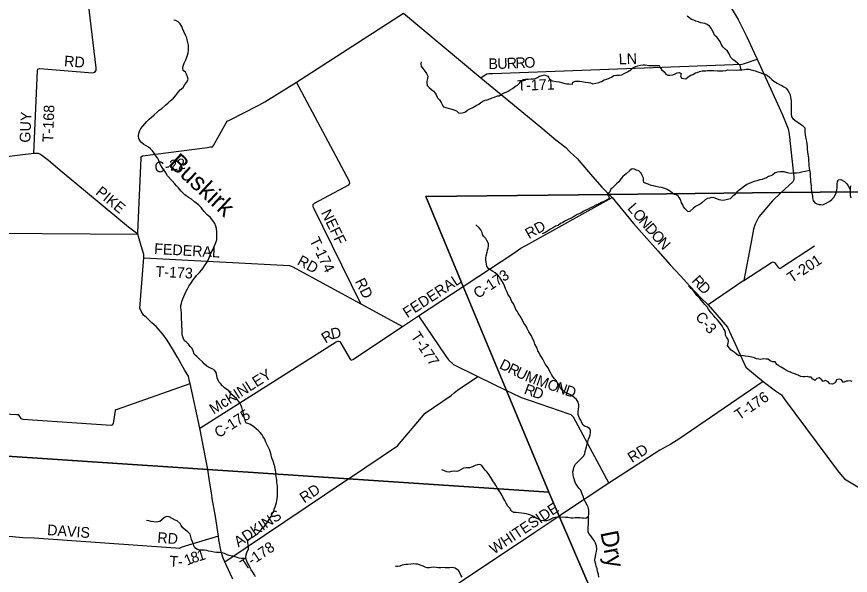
# Model space of a CAD drawing. Extents: x 1643459 to 2064572, y 425441 to 780708.
# Drawn here: x 1766596 to 1790021, y 620966 to 636662 of the extents above; entities that cross this region are included whole.
import ezdxf

# ---------------------------------------------------------------- set-up
doc = ezdxf.new("R2010")
doc.units = 0
for name, color, linetype in [('GM_X_City_Street', 7, 'Continuous'), ('GM_X_Interchange_Ramps', 7, 'Continuous'), ('GM_X_Major_River', 7, 'Continuous'), ('GM_X_Major_River_Text', 7, 'Continuous'), ('GM_X_Minor_Lake', 7, 'Continuous'), ('GM_X_Section_Text', 7, 'Continuous'), ('GM_X_US_Route', 7, 'Continuous')]:
    doc.layers.add(name, color=color, linetype=linetype)

msp = doc.modelspace()

# ---------------------------------------------------------------- linework, layer by layer
at = {"layer": 'GM_X_City_Street'}
for points in [[(1790269, 631741), (1788081, 631718), (1783242, 631666), (1778092, 631612), (1779143, 629082), (1780359, 626159), (1781545, 623306), (1775923, 623680), (1771965, 623943), (1758715, 624823), (1757178, 624925), (1757203, 625316), (1757453, 629228), (1757708, 633208), (1757977, 636642), (1758154, 639332)], [(1790575, 602316), (1789055, 605851), (1787632, 609158), (1785470, 614182), (1781837, 622626), (1781545, 623306), (1780359, 626159), (1779143, 629082), (1778092, 631612), (1783242, 631666), (1788081, 631718), (1790269, 631741)], [(1755032, 592905), (1755763, 604727), (1756758, 618359), (1756763, 618445), (1757178, 624925), (1758715, 624823), (1771965, 623943), (1775923, 623680), (1781545, 623306), (1781837, 622626), (1785470, 614182), (1787632, 609158), (1789055, 605851), (1790575, 602316), (1791118, 601055), (1793558, 602184), (1795084, 602890), (1794631, 595981)]]:
    msp.add_lwpolyline(points, dxfattribs=at)
at = {"layer": 'GM_X_Major_River_Text'}
for points in [[(1767083, 632818), (1767179, 635150), (1767195, 635186), (1767247, 635204), (1768723, 635088), (1768794, 635100), (1768826, 635150), (1768828, 635224), (1768475, 638203), (1767992, 642727)], [(1779643, 634945), (1779761, 635027), (1779809, 635055), (1779864, 635069), (1779976, 635068), (1786986, 635330), (1787052, 635344), (1787403, 635467)], [(1776267, 628598), (1774935, 631300), (1774929, 631339), (1774929, 631387), (1774969, 631421), (1775926, 631941), (1775954, 631971), (1775952, 632031), (1774462, 634825)], [(1787032, 629249), (1787808, 629758), (1787852, 629776), (1787892, 629758), (1788003, 629603), (1788043, 629589), (1788071, 629602), (1789018, 630222)], [(1770165, 629889), (1774267, 629667), (1774337, 629647), (1776267, 628598), (1777440, 627960)], [(1777890, 628257), (1778654, 627128), (1778733, 627019), (1778875, 626890), (1779559, 626553), (1780359, 626159), (1780500, 626092)], [(1775816, 623609), (1775923, 623680), (1777298, 624601), (1778078, 625524), (1778808, 626018), (1778887, 626097), (1778985, 626171), (1779559, 626553)], [(1787576, 626408), (1785201, 624793), (1784978, 624653), (1784670, 624480), (1783239, 623558), (1781934, 622690)], [(1758421, 625192), (1759118, 625175), (1759180, 625174), (1759214, 625196), (1759235, 625280), (1759284, 625860), (1759310, 625902), (1759370, 625900), (1766599, 625487), (1766639, 625483), (1766717, 625372), (1766771, 625352), (1769252, 625185), (1769288, 625191), (1769317, 625233), (1769369, 625594), (1769393, 625623), (1769429, 625637), (1771468, 626355)], [(1780500, 626092), (1780771, 625964), (1781023, 625874), (1782111, 625502), (1782165, 625485), (1782233, 625415), (1783239, 623558)], [(1772443, 621349), (1775816, 623609)], [(1772265, 622062), (1771334, 621784), (1771222, 621751), (1771159, 621721), (1771061, 621727), (1767086, 622006), (1766767, 622024), (1766477, 622043), (1766074, 622089), (1765375, 622185), (1764879, 622258), (1764486, 622292), (1763829, 622329), (1762692, 622399), (1762500, 622430), (1762426, 622474), (1762366, 622549), (1762350, 622609), (1762308, 622615), (1760568, 622684)], [(1781934, 622690), (1781837, 622626), (1781604, 622471), (1781160, 622171), (1779067, 620775), (1773925, 617348)]]:
    msp.add_lwpolyline(points, dxfattribs=at)
at = {"layer": 'GM_X_Minor_Lake'}
for points in [[(1786244, 637616), (1786618, 637001), (1786872, 636581), (1787110, 636098), (1787316, 635642), (1787403, 635467), (1788112, 633901), (1788235, 633607), (1788278, 633507), (1788306, 633358), (1788432, 632153), (1788432, 632075), (1788402, 632022), (1788081, 631718), (1787834, 631484), (1787452, 631039), (1787349, 630830), (1787339, 630801)], [(1770002, 630601), (1770093, 632687), (1770093, 632721), (1770134, 632749), (1771962, 632990), (1772032, 633004), (1772074, 633002), (1772101, 633006), (1772127, 633040), (1772487, 633676), (1772513, 633722), (1772573, 633755), (1773397, 634171), (1773574, 634266), (1774462, 634825), (1777468, 636763)], [(1777468, 636763), (1779643, 634945), (1780949, 633862), (1781378, 633511), (1781747, 633198), (1782023, 632988), (1782140, 632869), (1782345, 632675), (1782447, 632557), (1782718, 632238), (1783038, 631872), (1783242, 631666), (1783288, 631620)], [(1770000, 630549), (1769738, 630751), (1767875, 632293), (1767488, 632617), (1767305, 632763), (1767251, 632801), (1767205, 632821), (1767083, 632818), (1766239, 632718), (1766124, 632716), (1765966, 632741), (1765594, 632819), (1764734, 633082), (1764288, 633225), (1763876, 633369), (1762914, 633685), (1762390, 633870), (1761928, 634031), (1761582, 634167), (1760684, 634572), (1760184, 634781)], [(1779254, 629155), (1780534, 629999), (1780767, 630154), (1780900, 630229), (1783325, 631583)], [(1783288, 631620), (1783325, 631583), (1783925, 630854), (1784231, 630514), (1784608, 630087), (1784962, 629692), (1785249, 629378), (1785510, 629088), (1785835, 628745), (1786024, 628565)], [(1758569, 629508), (1760488, 630050), (1760613, 630088), (1760956, 630230), (1761763, 630549), (1761833, 630579), (1761938, 630603), (1770000, 630549), (1770002, 630601), (1770002, 630601)], [(1787339, 630801), (1787339, 630800), (1787302, 630689), (1787221, 630277), (1787032, 629249), (1786024, 628565)], [(1772076, 623215), (1772076, 623217), (1772011, 623620), (1771965, 623943), (1771740, 625096), (1771468, 626355), (1771455, 626416), (1771421, 626560), (1771326, 626717), (1771121, 627073), (1770977, 627329), (1770828, 627572), (1770702, 627737), (1770513, 627957), (1770393, 628064), (1770234, 628221), (1770164, 628280), (1770095, 628390), (1770059, 628469), (1770162, 629778), (1770165, 629889), (1770167, 629978), (1770096, 630222), (1770000, 630549)], [(1777440, 627960), (1777890, 628257), (1779143, 629082), (1779254, 629155)], [(1786024, 628565), (1786568, 627941), (1787089, 626817), (1787576, 626408), (1787923, 626151), (1788091, 626036), (1788162, 625929), (1789662, 623912), (1789748, 623811), (1789861, 623680), (1791597, 622627), (1791717, 622548), (1791760, 622488), (1791917, 622258), (1792684, 620737), (1793347, 619452), (1794514, 618662)], [(1771740, 625096), (1775578, 627522), (1775616, 627544), (1775642, 627548), (1775680, 627538), (1775970, 627043), (1775996, 627012), (1776044, 627034), (1777440, 627960)], [(1772673, 620857), (1772481, 621261), (1772443, 621349), (1772402, 621446), (1772347, 621623), (1772281, 621964), (1772265, 622062), (1772180, 622617), (1772090, 623129), (1772076, 623215)]]:
    msp.add_lwpolyline(points, dxfattribs=at)
at = {"layer": 'GM_X_US_Route'}
for points in [[(1772105, 630112), (1772145, 630202), (1772180, 630285), (1772217, 630393), (1772225, 630461), (1772218, 630519), (1772221, 630620), (1772215, 630710), (1772194, 630778), (1772160, 630847), (1772103, 630941), (1772031, 631028), (1771949, 631095), (1771864, 631192), (1771822, 631244), (1771778, 631299), (1771715, 631367), (1771663, 631410), (1771589, 631458), (1771507, 631531), (1771421, 631584), (1771324, 631658), (1771216, 631763), (1771139, 631854), (1771087, 631911), (1771043, 631967), (1770970, 632054), (1770838, 632187), (1770789, 632270), (1770757, 632320), (1770725, 632370), (1770687, 632425), (1770634, 632501), (1770608, 632564), (1770581, 632644), (1770557, 632699), (1770501, 632763), (1770462, 632830), (1770412, 632892), (1770360, 632945), (1770298, 632993), (1770237, 633030), (1770173, 633066), (1770101, 633125), (1770051, 633189), (1770025, 633239), (1770024, 633312), (1770033, 633384), (1770059, 633468), (1770088, 633522), (1770142, 633586), (1770193, 633650), (1770253, 633714), (1770316, 633778), (1770389, 633838), (1770457, 633908), (1770540, 633981), (1770603, 634031), (1770675, 634085), (1770774, 634177), (1770849, 634243), (1770913, 634297), (1771000, 634374), (1771057, 634438), (1771146, 634548), (1771192, 634602), (1771273, 634674), (1771321, 634752), (1771380, 634820), (1771411, 634910), (1771397, 634972), (1771366, 635049), (1771336, 635101), (1771276, 635154), (1771267, 635222), (1771273, 635272), (1771300, 635352), (1771346, 635449), (1771381, 635521), (1771397, 635581), (1771414, 635649), (1771427, 635717), (1771429, 635787), (1771420, 635862), (1771406, 635938), (1771387, 636014), (1771373, 636071), (1771337, 636141), (1771292, 636244), (1771260, 636326), (1771237, 636383), (1771187, 636457), (1771131, 636514), (1771070, 636556), (1771011, 636561)], [(1786953, 635171), (1786923, 635287), (1786863, 635349), (1786785, 635408), (1786716, 635460), (1786664, 635513), (1786632, 635569), (1786611, 635638), (1786569, 635694), (1786503, 635747), (1786437, 635811), (1786396, 635888), (1786360, 635960), (1786329, 636012), (1786275, 636079), (1786205, 636138), (1786172, 636222), (1786140, 636287), (1786112, 636337), (1786063, 636391), (1785999, 636444), (1785933, 636470), (1785881, 636483), (1785817, 636493), (1785755, 636521), (1785679, 636538), (1785627, 636560), (1785561, 636585), (1785437, 636672)], [(1777961, 635396), (1777957, 635331), (1777966, 635273), (1778010, 635203), (1778076, 635126), (1778109, 635070), (1778145, 634993), (1778142, 634925), (1778126, 634853), (1778121, 634798), (1778129, 634732), (1778191, 634668), (1778254, 634613), (1778306, 634571), (1778356, 634514), (1778384, 634464), (1778423, 634383), (1778479, 634323), (1778527, 634252), (1778550, 634190), (1778594, 634133), (1778658, 634111), (1778746, 634084), (1778798, 634070), (1778854, 634054), (1778904, 634039), (1778958, 634019), (1779014, 633962), (1779078, 633950), (1779186, 633976), (1779263, 634031), (1779331, 634075), (1779410, 634109), (1779506, 634164), (1779581, 634206), (1779637, 634250), (1779694, 634288), (1779762, 634314), (1779816, 634321), (1779891, 634349), (1779959, 634383), (1780023, 634397), (1780106, 634436), (1780156, 634442), (1780206, 634474), (1780295, 634522), (1780355, 634537), (1780410, 634573), (1780466, 634603), (1780528, 634645), (1780615, 634706), (1780673, 634736), (1780726, 634792), (1780774, 634852), (1780831, 634896), (1780895, 634906), (1780965, 634909), (1781052, 634913), (1781118, 634915), (1781172, 634926), (1781232, 634956), (1781287, 634986), (1781365, 635012), (1781427, 635031), (1781521, 634993), (1781549, 634942), (1781591, 634876), (1781653, 634859), (1781753, 634843), (1781839, 634832), (1781903, 634814), (1781997, 634787), (1782057, 634773), (1782115, 634777), (1782211, 634768), (1782228, 634818), (1782302, 634854), (1782364, 634852), (1782421, 634851), (1782473, 634841), (1782523, 634833), (1782583, 634824), (1782665, 634808), (1782717, 634803), (1782785, 634779), (1782873, 634791), (1782956, 634810), (1783032, 634840), (1783107, 634888), (1783175, 634907), (1783243, 634931), (1783310, 634963), (1783380, 635013), (1783458, 635014), (1783527, 635014), (1783603, 635030), (1783665, 635061), (1783762, 635115), (1783852, 635173), (1783913, 635223), (1783983, 635266)], [(1783983, 635266), (1784054, 635282), (1784124, 635304), (1784202, 635311), (1784258, 635307), (1784359, 635292), (1784539, 635291), (1784647, 635289), (1784675, 635236), (1784713, 635180), (1784790, 635111), (1784840, 635049), (1784892, 635019), (1784950, 635018), (1785036, 635026), (1785097, 635058), (1785153, 635081), (1785213, 635089), (1785265, 635061), (1785253, 635000), (1785278, 634932), (1785399, 634915), (1785469, 634971), (1785538, 635021), (1785592, 635037), (1785666, 635081), (1785717, 635092), (1785785, 635120), (1785857, 635140), (1785909, 635143), (1785960, 635143), (1786012, 635145), (1786078, 635149), (1786136, 635154), (1786190, 635152), (1786290, 635143), (1786346, 635141), (1786443, 635143), (1786527, 635154), (1786581, 635164), (1786814, 635163), (1786898, 635164), (1786970, 635172), (1787045, 635182), (1787099, 635185), (1787173, 635185), (1787271, 635160), (1787345, 635140), (1787419, 635109), (1787483, 635089), (1787557, 635064), (1787619, 635048), (1787687, 635023), (1787759, 634957), (1787816, 634896), (1787874, 634848), (1787970, 634793), (1788030, 634759), (1788092, 634732), (1788150, 634694), (1788214, 634651), (1788261, 634585), (1788305, 634524), (1788329, 634470), (1788338, 634390), (1788356, 634297), (1788357, 634237), (1788355, 633986), (1788357, 633934), (1788368, 633847), (1788408, 633797), (1788460, 633751), (1788610, 633651), (1788675, 633609), (1788739, 633536), (1788739, 633482), (1788740, 633418), (1788756, 633343), (1788763, 633275), (1788781, 633201), (1788791, 633150), (1788796, 633098), (1788808, 633000), (1788813, 632940), (1788819, 632867), (1788826, 632803), (1788840, 632747), (1788843, 632692), (1788849, 632616), (1788854, 632536), (1788858, 632486), (1788867, 632395), (1788881, 632319), (1788888, 632241), (1788894, 632180), (1788901, 632080), (1788905, 632024), (1788911, 631971), (1788918, 631911), (1788925, 631823), (1788931, 631769)], [(1788877, 632340), (1788833, 632329), (1788751, 632310), (1788652, 632292), (1788584, 632276), (1788512, 632269), (1788437, 632265), (1788371, 632257), (1788289, 632262), (1788221, 632284), (1788161, 632307), (1788111, 632307), (1788053, 632303), (1787978, 632292), (1787908, 632276), (1787840, 632220), (1787783, 632194), (1787725, 632167), (1787665, 632135), (1787614, 632113), (1787546, 632091), (1787476, 632080), (1787393, 632054), (1787323, 632034), (1787247, 632005), (1787182, 631979), (1787114, 631945), (1787049, 631899), (1786967, 631839), (1786898, 631790), (1786836, 631732), (1786771, 631660), (1786704, 631604), (1786642, 631546), (1786569, 631522), (1786499, 631505), (1786437, 631499), (1786385, 631505), (1786335, 631518), (1786273, 631540), (1786191, 631575), (1786119, 631579), (1786061, 631565), (1786010, 631554), (1785938, 631514), (1785851, 631430), (1785801, 631396), (1785730, 631358), (1785666, 631333), (1785605, 631275), (1785519, 631197), (1785460, 631175), (1785377, 631260), (1785337, 631320), (1785319, 631373), (1785278, 631431), (1785252, 631521), (1785197, 631606), (1785141, 631653), (1785075, 631669), (1785021, 631703), (1784967, 631754), (1784871, 631807), (1784809, 631831), (1784755, 631849), (1784705, 631862), (1784637, 631870), (1784557, 631889), (1784487, 631907), (1784429, 631923), (1784345, 631956), (1784285, 631978), (1784221, 632003), (1784209, 632055), (1784208, 632123), (1784170, 632204), (1784141, 632266), (1784083, 632333), (1784009, 632349), (1783953, 632374), (1783893, 632390), (1783824, 632336), (1783725, 632244), (1783631, 632175), (1783572, 632107), (1783513, 632025), (1783455, 631969), (1783390, 631907), (1783338, 631857), (1783287, 631813), (1783251, 631725), (1783192, 631675), (1783230, 631625), (1783255, 631556), (1783201, 631529), (1783137, 631491), (1783074, 631459), (1783024, 631437), (1782958, 631401), (1782855, 631356), (1782785, 631320)], [(1788931, 631769), (1788939, 631700), (1788954, 631620), (1788960, 631570), (1788973, 631499), (1789021, 631427), (1789077, 631408), (1789143, 631388), (1789195, 631384), (1789251, 631373), (1789324, 631417), (1789376, 631437), (1789442, 631475), (1789503, 631529), (1789572, 631609), (1789622, 631709), (1789645, 631797), (1789656, 631849), (1789650, 631915), (1789650, 631965), (1789657, 632020), (1789683, 632074), (1789753, 632091), (1789853, 632031), (1789925, 631968), (1789961, 631906), (1790015, 631810)], [(1790025, 631911), (1790016, 631833), (1790012, 631745), (1790015, 631692), (1790021, 631638), (1790032, 631570)], [(1782785, 631320), (1782724, 631290), (1782652, 631253), (1782585, 631221), (1782517, 631185), (1782448, 631141), (1782350, 631100), (1782292, 631066), (1782241, 631040), (1782189, 631004), (1782116, 630974), (1782018, 630923), (1781945, 630879), (1781879, 630847), (1781808, 630799), (1781738, 630776), (1781676, 630736), (1781599, 630688), (1781537, 630652), (1781484, 630618), (1781434, 630593), (1781362, 630565)], [(1782612, 624574), (1782629, 624660), (1782644, 624716), (1782668, 624788), (1782693, 624858), (1782707, 624910), (1782724, 624969), (1782724, 625035), (1782698, 625085), (1782632, 625126), (1782572, 625144), (1782517, 625189), (1782479, 625255), (1782445, 625325), (1782412, 625378), (1782392, 625430), (1782378, 625482), (1782377, 625561), (1782381, 625643), (1782392, 625697), (1782390, 625755), (1782363, 625850), (1782327, 625902), (1782269, 625955), (1782198, 626015), (1782120, 626056), (1782052, 626088), (1781986, 626125), (1781932, 626169), (1781878, 626238), (1781855, 626294), (1781791, 626371), (1781763, 626429), (1781702, 626498), (1781638, 626591), (1781607, 626649), (1781569, 626713), (1781529, 626796), (1781460, 626887), (1781432, 626947), (1781393, 627018), (1781355, 627084), (1781305, 627154), (1781274, 627213), (1781240, 627273), (1781217, 627350), (1781159, 627460), (1781138, 627537), (1781090, 627623), (1781067, 627692), (1781021, 627752), (1780985, 627811), (1780942, 627899), (1780910, 627970), (1780845, 628054), (1780817, 628115), (1780783, 628185), (1780746, 628250), (1780690, 628330), (1780656, 628385), (1780625, 628437), (1780591, 628511), (1780552, 628592), (1780512, 628660), (1780480, 628725), (1780451, 628793), (1780411, 628848), (1780374, 628926), (1780344, 628995), (1780305, 629099), (1780273, 629162), (1780233, 629238), (1780170, 629335), (1780112, 629403), (1780039, 629468), (1779977, 629501), (1779865, 629577), (1779805, 629644), (1779796, 629716), (1779788, 629769), (1779780, 629827), (1779783, 629887), (1779787, 629941), (1779814, 630047), (1779830, 630102), (1779845, 630158), (1779855, 630214), (1779858, 630286), (1779810, 630377), (1779777, 630431), (1779715, 630494), (1779687, 630544), (1779676, 630596), (1779640, 630677), (1779590, 630727), (1779497, 630814)], [(1773921, 623489), (1773911, 623561), (1773904, 623628), (1773898, 623692), (1773888, 623748), (1773883, 623802), (1773877, 623865), (1773870, 623917), (1773852, 624017), (1773835, 624082), (1773803, 624174), (1773778, 624241), (1773760, 624293), (1773746, 624347), (1773725, 624416), (1773697, 624502), (1773662, 624579), (1773628, 624651), (1773602, 624705), (1773567, 624790), (1773525, 624854), (1773496, 624915), (1773436, 624981), (1773378, 625038), (1773322, 625084), (1773257, 625135), (1773163, 625200), (1773093, 625236), (1773033, 625249), (1773013, 625321), (1772992, 625402), (1772970, 625488), (1772957, 625556), (1772943, 625609), (1772926, 625677), (1772896, 625753), (1772866, 625808), (1772831, 625860), (1772769, 625935), (1772717, 625981), (1772639, 626050), (1772554, 626147), (1772436, 626230), (1772378, 626292), (1772321, 626351), (1772275, 626403), (1772253, 626464), (1772228, 626516), (1772220, 626578), (1772205, 626663), (1772159, 626727), (1772091, 626770), (1772023, 626792), (1771943, 626847), (1771860, 626912), (1771814, 626964), (1771734, 627043), (1771654, 627113), (1771585, 627182), (1771551, 627271), (1771528, 627335), (1771474, 627396), (1771426, 627460), (1771367, 627517), (1771309, 627559), (1771273, 627638), (1771248, 627722), (1771246, 627818), (1771243, 627897), (1771237, 627947), (1771234, 628017), (1771234, 628079), (1771231, 628142), (1771227, 628232), (1771230, 628296), (1771226, 628355), (1771220, 628405), (1771209, 628497), (1771211, 628549), (1771226, 628607), (1771236, 628664), (1771261, 628738), (1771289, 628804), (1771330, 628882), (1771361, 628948), (1771393, 629012), (1771436, 629090), (1771488, 629168), (1771557, 629272), (1771606, 629328), (1771646, 629390), (1771733, 629478), (1771796, 629552), (1771843, 629612), (1771877, 629662), (1771938, 629752), (1771978, 629822), (1772011, 629910), (1772031, 629962), (1772056, 630014), (1772105, 630112)], [(1786538, 627658), (1786512, 627712), (1786517, 627777), (1786495, 627845), (1786462, 627901), (1786416, 627974), (1786352, 628061), (1786293, 628145), (1786229, 628204), (1786185, 628254), (1786112, 628343), (1786038, 628444), (1786001, 628510), (1785931, 628579), (1785883, 628635), (1785828, 628698), (1785770, 628774), (1785704, 628831), (1785653, 628910), (1785603, 628966), (1785545, 629029), (1785482, 629101)], [(1790074, 626416), (1790012, 626433), (1789952, 626421), (1789902, 626417), (1789833, 626386), (1789772, 626454), (1789708, 626477), (1789637, 626461), (1789601, 626385), (1789518, 626335), (1789448, 626343), (1789394, 626406), (1789320, 626438), (1789258, 626415), (1789204, 626479), (1789145, 626514), (1789084, 626500), (1789022, 626440), (1788968, 626477), (1788918, 626529), (1788868, 626537), (1788806, 626554), (1788742, 626542), (1788686, 626542), (1788630, 626555), (1788572, 626577), (1788504, 626606), (1788400, 626644), (1788340, 626673), (1788284, 626697), (1788232, 626723), (1788174, 626756), (1788076, 626813), (1788014, 626855), (1787952, 626888), (1787909, 626960), (1787832, 626967), (1787766, 626993), (1787709, 627043), (1787653, 627040), (1787580, 627050), (1787506, 627033), (1787452, 627039), (1787382, 627051), (1787326, 627074), (1787254, 627096), (1787160, 627111), (1787068, 627123), (1787018, 627132), (1786947, 627138), (1786887, 627132), (1786823, 627181), (1786758, 627239), (1786676, 627290), (1786620, 627355), (1786573, 627423), (1786591, 627489), (1786601, 627541), (1786580, 627606), (1786538, 627658)], [(1782953, 620912), (1782944, 620988), (1782920, 621071), (1782907, 621147), (1782881, 621219), (1782866, 621280), (1782854, 621336), (1782845, 621404), (1782859, 621495), (1782872, 621563), (1782888, 621637), (1782901, 621709), (1782889, 621796), (1782858, 621874), (1782820, 621945), (1782769, 622017), (1782727, 622076), (1782671, 622142), (1782658, 622192), (1782654, 622259), (1782653, 622321), (1782661, 622403), (1782666, 622459), (1782667, 622620), (1782669, 622672), (1782674, 622736), (1782672, 622803), (1782657, 622877), (1782625, 622939), (1782569, 623042), (1782532, 623113), (1782526, 623165), (1782479, 623277), (1782447, 623358), (1782392, 623418), (1782352, 623473), (1782302, 623560), (1782281, 623614), (1782259, 623674), (1782244, 623726), (1782230, 623803), (1782227, 623875), (1782239, 623941), (1782262, 624028), (1782298, 624086), (1782365, 624155), (1782440, 624233), (1782520, 624315), (1782563, 624379), (1782573, 624441), (1782592, 624512), (1782612, 624574)], [(1782667, 622620), (1782588, 622566), (1782520, 622575), (1782470, 622575), (1782420, 622577), (1782354, 622579), (1782294, 622578), (1782237, 622576), (1782171, 622576), (1782079, 622589), (1782015, 622595), (1781891, 622596), (1781829, 622604), (1781736, 622595), (1781674, 622577), (1781608, 622545), (1781547, 622514), (1781481, 622494), (1781405, 622494), (1781325, 622507), (1781261, 622547), (1781195, 622572), (1781119, 622620), (1781045, 622655), (1780983, 622677), (1780911, 622698), (1780857, 622704), (1780781, 622711), (1780700, 622719), (1780624, 622727), (1780562, 622730), (1780498, 622768), (1780449, 622851), (1780397, 622911), (1780352, 622992), (1780314, 623064), (1780264, 623145), (1780237, 623205), (1780181, 623298), (1780144, 623348), (1780106, 623407), (1780074, 623477), (1780027, 623552), (1779979, 623624), (1779918, 623713), (1779870, 623786), (1779818, 623862), (1779765, 623923), (1779701, 623991), (1779665, 624054), (1779609, 624080), (1779541, 624070), (1779481, 624049), (1779406, 624017), (1779320, 623987), (1779222, 623986), (1779151, 623980), (1779089, 623936), (1779019, 623899), (1778966, 623885), (1778890, 623891), (1778818, 623882), (1778748, 623866), (1778680, 623874), (1778622, 623905), (1778540, 623931)], [(1773305, 620920), (1773275, 620979), (1773232, 621051), (1773190, 621120), (1773156, 621180), (1773117, 621259), (1773071, 621337), (1773050, 621396), (1773038, 621468), (1773045, 621538), (1773067, 621612), (1773108, 621707), (1773108, 621771), (1773101, 621821), (1773089, 621885), (1773088, 621956), (1773168, 622009), (1773225, 622041), (1773307, 622093), (1773368, 622139), (1773448, 622213), (1773499, 622289), (1773560, 622351), (1773624, 622433), (1773716, 622577), (1773752, 622631), (1773779, 622693), (1773821, 622763), (1773834, 622823), (1773862, 622893), (1773879, 622943), (1773897, 623009), (1773906, 623063), (1773916, 623128), (1773923, 623190), (1773925, 623258), (1773926, 623367), (1773922, 623429), (1773921, 623489)], [(1773048, 621423), (1772984, 621438), (1772916, 621441), (1772850, 621451), (1772739, 621482), (1772673, 621504), (1772571, 621523), (1772509, 621545), (1772433, 621582), (1772365, 621602), (1772291, 621611), (1772215, 621611), (1772145, 621620), (1772057, 621632), (1771989, 621642), (1771937, 621661), (1771873, 621669), (1771798, 621674), (1771744, 621676), (1771674, 621692), (1771602, 621735), (1771575, 621799), (1771561, 621854), (1771541, 621906), (1771512, 621976), (1771486, 622051), (1771475, 622119), (1771403, 622186), (1771337, 622236), (1771263, 622303), (1771216, 622362), (1771194, 622424), (1771110, 622495), (1771050, 622515), (1770965, 622566), (1770885, 622612), (1770805, 622617), (1770752, 622593), (1770678, 622527), (1770621, 622483), (1770563, 622468), (1770499, 622464), (1770449, 622466), (1770376, 622483), (1770306, 622501), (1770248, 622505)], [(1777867, 621277), (1777809, 621283), (1777747, 621285), (1777669, 621282), (1777582, 621272), (1777532, 621269), (1777478, 621259), (1777426, 621247), (1777365, 621227), (1777303, 621218), (1777237, 621216)], [(1779116, 620917), (1779080, 620969), (1779050, 621033), (1779009, 621104), (1778917, 621167), (1778847, 621187), (1778767, 621180), (1778632, 621180), (1778568, 621183), (1778512, 621179), (1778444, 621179), (1778380, 621188), (1778316, 621192), (1778243, 621184), (1778193, 621175), (1778127, 621175), (1778077, 621191), (1778017, 621222), (1777935, 621254), (1777867, 621277)]]:
    msp.add_lwpolyline(points, dxfattribs=at)

# ---------------------------------------------------------------- texts
at = {"layer": 'GM_X_Interchange_Ramps'}
for s, rotation, p in [('Buskirk', 317.1157, (1770829, 632503)), ('Dry', 281.1141, (1782995, 622171))]:
    msp.add_text(s, height=500, rotation=rotation, dxfattribs=at).set_placement(p)
at = {"layer": 'GM_X_Major_River'}
for s, rotation, p in [('RD', 355.5641, (1767921, 635271)), ('R', 2.1784, (1780617, 635213)), ('O', 2.1753, (1780864, 635222)), ('LN', 2.0627, (1783519, 635320)), ('B', 1.171, (1779855, 635188)), ('U', 2.136, (1780107, 635193)), ('R', 2.1786, (1780371, 635203)), ('T-171', 2.2467, (1780670, 634576)), ('T-168', 87.7539, (1767618, 633131)), ('GUY', 87.4688, (1766976, 633117)), ('NEFF', 296.1879, (1775140, 631157)), ('T-174', 296.1874, (1774815, 630379)), ('FEDERAL', 356.7862, (1770453, 629996)), ('RD', 331.2323, (1774457, 629714)), ('T-201', 33.2233, (1788371, 629174)), ('T-173', 356.913, (1770493, 629358)), ('RD', 296.5659, (1776095, 629226)), ('T-177', 303.8453, (1777657, 627683)), ('D', 333.8211, (1780136, 626791)), ('R', 333.819, (1780373, 626675)), ('U', 333.8182, (1780595, 626566)), ('M', 338.8727, (1780858, 626438)), ('M', 341.0117, (1781173, 626316)), ('O', 340.9799, (1781481, 626211)), ('N', 340.9812, (1781731, 626125)), ('R', 340.248, (1780833, 626075)), ('D', 340.6392, (1781067, 625991)), ('D', 341.4715, (1781983, 626038)), ('T-176', 34.2348, (1786896, 625316)), ('RD', 32.7352, (1783886, 624116)), ('RD', 33.8266, (1774675, 622984)), ('WHITESIDE', 33.7245, (1780008, 621546)), ('ADKINS', 33.8423, (1772827, 621748)), ('DAVIS', 355.9628, (1767445, 622098)), ('RD', 356.0551, (1770542, 621882)), ('T-178', 34.0014, (1773008, 621099)), ('T', 356.1829, (1770880, 621219)), ('1', 23.5709, (1771380, 621232)), ('8', 17.4302, (1771541, 621303)), ('1', 17.0978, (1771717, 621358)), ('-', 0.9956, (1771131, 621203))]:
    msp.add_text(s, height=300, rotation=rotation, dxfattribs=at).set_placement(p)
at = {"layer": 'GM_X_Section_Text'}
for s, rotation, p in [('C-22', 7.9352, (1770492, 632270)), ('PIKE', 320.2739, (1768793, 631693)), ('L', 310.863, (1783741, 631270)), ('O', 310.8597, (1783887, 631100)), ('N', 310.8612, (1784060, 630901)), ('RD', 29.4386, (1780990, 630409)), ('D', 310.8639, (1784233, 630701)), ('O', 310.8798, (1784406, 630501)), ('N', 311.7559, (1784582, 630298)), ('C-173', 33.2323, (1779554, 628729)), ('FEDERAL', 33.351, (1777573, 628187)), ('R', 312.5596, (1785545, 629228)), ('D', 313.3442, (1785715, 629043)), ('C-3', 310.8004, (1785645, 628213)), ('R', 32.0856, (1775276, 627474)), ('D', 13.7897, (1775462, 627595)), ('McKINLEY', 32.3665, (1772130, 625480)), ('C-175', 32.4713, (1772271, 624814))]:
    msp.add_text(s, height=300, rotation=rotation, dxfattribs=at).set_placement(p)

doc.saveas('drawing.dxf')
